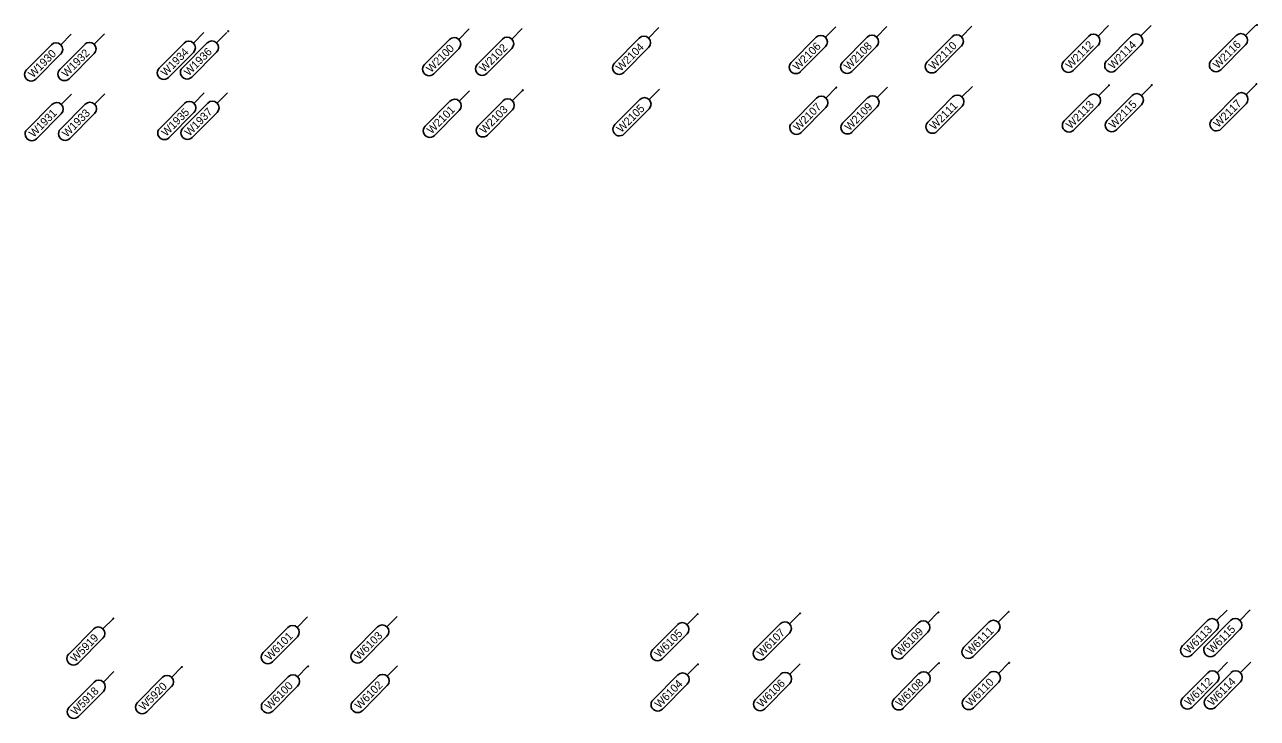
# Model space of a CAD drawing. Extents: x 12479652 to 12487250, y 9842710 to 9846560.
# Drawn here: x 12483450.8 to 12483643.4, y 9842744 to 9842852.3 of the extents above; entities that cross this region are included whole.
import ezdxf

# ---------------------------------------------------------------- set-up
doc = ezdxf.new("R2010")
doc.units = 0
doc.layers.add('_CIVIL_CONSTRUCTION', color=7, linetype='Continuous')
doc.layers.add('TextAlignmentLrg', color=7, linetype='Continuous')

msp = doc.modelspace()

# ---------------------------------------------------------------- linework, layer by layer
at = {"layer": '_CIVIL_CONSTRUCTION'}
for p, q in [((12483478.81, 9842851.1), (12483477.19, 9842849.47)), ((12483482.43, 9842851.14), (12483480.81, 9842849.51)), ((12483520.26, 9842851.67), (12483518.64, 9842850.04)), ((12483528.55, 9842851.73), (12483526.93, 9842850.1)), ((12483549.91, 9842851.88), (12483548.29, 9842850.25)), ((12483577.52, 9842852.01), (12483575.9, 9842850.37)), ((12483585.52, 9842852.04), (12483583.9, 9842850.41)), ((12483598.78, 9842852.1), (12483597.16, 9842850.47)), ((12483620.1, 9842852.2), (12483618.48, 9842850.57)), ((12483626.8, 9842852.23), (12483625.18, 9842850.6)), ((12483643.14, 9842852.28), (12483641.52, 9842850.65)), ((12483451.14, 9842845.3), (12483455.03, 9842849.21)), ((12483456.34, 9842845.36), (12483460.23, 9842849.27)), ((12483458.1, 9842850.85), (12483456.48, 9842849.22)), ((12483463.3, 9842850.91), (12483461.68, 9842849.28)), ((12483471.85, 9842845.55), (12483475.74, 9842849.46)), ((12483475.47, 9842845.59), (12483479.36, 9842849.51)), ((12483513.3, 9842846.12), (12483517.19, 9842850.04)), ((12483521.59, 9842846.18), (12483525.48, 9842850.09)), ((12483542.95, 9842846.33), (12483546.84, 9842850.24)), ((12483570.56, 9842846.46), (12483574.45, 9842850.37)), ((12483578.56, 9842846.49), (12483582.45, 9842850.41)), ((12483591.82, 9842846.55), (12483595.7, 9842850.47)), ((12483613.14, 9842846.65), (12483617.03, 9842850.56)), ((12483619.84, 9842846.68), (12483623.73, 9842850.59)), ((12483625.18, 9842849.15), (12483621.29, 9842845.23)), ((12483636.18, 9842846.73), (12483640.07, 9842850.64)), ((12483641.52, 9842849.2), (12483637.64, 9842845.28)), ((12483456.48, 9842847.77), (12483452.59, 9842843.85)), ((12483461.69, 9842847.83), (12483457.8, 9842843.91)), ((12483477.2, 9842848.01), (12483473.31, 9842844.1)), ((12483480.82, 9842848.06), (12483476.93, 9842844.15)), ((12483518.64, 9842848.59), (12483514.75, 9842844.68)), ((12483526.93, 9842848.65), (12483523.04, 9842844.73)), ((12483548.29, 9842848.8), (12483544.4, 9842844.88)), ((12483575.91, 9842848.92), (12483572.02, 9842845.01)), ((12483583.9, 9842848.96), (12483580.01, 9842845.05)), ((12483597.16, 9842849.02), (12483593.27, 9842845.11)), ((12483618.49, 9842849.12), (12483614.6, 9842845.2)), ((12483458.18, 9842841.52), (12483456.56, 9842839.89)), ((12483463.38, 9842841.57), (12483461.76, 9842839.93)), ((12483478.89, 9842841.69), (12483477.27, 9842840.06)), ((12483482.51, 9842841.72), (12483480.89, 9842840.09)), ((12483520.34, 9842842.04), (12483518.72, 9842840.41)), ((12483528.63, 9842842.11), (12483527.01, 9842840.48)), ((12483549.99, 9842842.29), (12483548.37, 9842840.65)), ((12483577.6, 9842842.51), (12483575.98, 9842840.88)), ((12483585.6, 9842842.58), (12483583.98, 9842840.95)), ((12483598.86, 9842842.69), (12483597.23, 9842841.06)), ((12483620.18, 9842842.87), (12483618.56, 9842841.24)), ((12483626.88, 9842842.92), (12483625.25, 9842841.29)), ((12483636.26, 9842837.51), (12483640.15, 9842841.42)), ((12483643.22, 9842843.06), (12483641.6, 9842841.43)), ((12483451.22, 9842835.97), (12483455.1, 9842839.89)), ((12483456.42, 9842836.02), (12483460.31, 9842839.93)), ((12483471.93, 9842836.15), (12483475.82, 9842840.06)), ((12483475.55, 9842836.18), (12483479.44, 9842840.09)), ((12483513.38, 9842836.49), (12483517.27, 9842840.4)), ((12483521.67, 9842836.56), (12483525.56, 9842840.47)), ((12483543.03, 9842836.74), (12483546.92, 9842840.65)), ((12483570.64, 9842836.97), (12483574.53, 9842840.88)), ((12483578.64, 9842837.03), (12483582.53, 9842840.95)), ((12483583.98, 9842839.5), (12483580.09, 9842835.59)), ((12483591.89, 9842837.14), (12483595.78, 9842841.06)), ((12483597.24, 9842839.61), (12483593.35, 9842835.7)), ((12483613.22, 9842837.32), (12483617.11, 9842841.23)), ((12483618.56, 9842839.79), (12483614.67, 9842835.87)), ((12483619.91, 9842837.38), (12483623.8, 9842841.29)), ((12483625.26, 9842839.84), (12483621.37, 9842835.93)), ((12483641.6, 9842839.98), (12483637.71, 9842836.06)), ((12483456.56, 9842838.44), (12483452.67, 9842834.53)), ((12483461.76, 9842838.48), (12483457.87, 9842834.57)), ((12483477.27, 9842838.61), (12483473.38, 9842834.7)), ((12483480.89, 9842838.64), (12483477, 9842834.73)), ((12483518.72, 9842838.96), (12483514.83, 9842835.04)), ((12483527.01, 9842839.03), (12483523.12, 9842835.11)), ((12483548.37, 9842839.2), (12483544.48, 9842835.29)), ((12483575.99, 9842839.43), (12483572.1, 9842835.52)), ((12483593.53, 9842760.59), (12483591.91, 9842758.96)), ((12483604.49, 9842760.68), (12483602.87, 9842759.04)), ((12483638.64, 9842760.93), (12483637.01, 9842759.3)), ((12483642.27, 9842760.96), (12483640.65, 9842759.33)), ((12483464.69, 9842759.63), (12483463.07, 9842758)), ((12483495.04, 9842759.86), (12483493.42, 9842758.23)), ((12483509.04, 9842759.96), (12483507.42, 9842758.33)), ((12483548.95, 9842754.76), (12483552.84, 9842758.68)), ((12483555.91, 9842760.31), (12483554.29, 9842758.68)), ((12483564.95, 9842754.88), (12483568.84, 9842758.8)), ((12483571.91, 9842760.43), (12483570.29, 9842758.8)), ((12483586.57, 9842755.04), (12483590.46, 9842758.96)), ((12483597.53, 9842755.13), (12483601.42, 9842759.04)), ((12483631.67, 9842755.38), (12483635.56, 9842759.29)), ((12483635.31, 9842755.41), (12483639.2, 9842759.32)), ((12483457.73, 9842754.08), (12483461.62, 9842758)), ((12483488.08, 9842754.31), (12483491.97, 9842758.22)), ((12483493.43, 9842756.78), (12483489.54, 9842752.86)), ((12483502.08, 9842754.41), (12483505.97, 9842758.33)), ((12483507.43, 9842756.88), (12483503.54, 9842752.97)), ((12483554.29, 9842757.23), (12483550.4, 9842753.32)), ((12483570.29, 9842757.35), (12483566.4, 9842753.44)), ((12483591.91, 9842757.51), (12483588.02, 9842753.6)), ((12483602.87, 9842757.59), (12483598.99, 9842753.68)), ((12483637.02, 9842757.85), (12483633.13, 9842753.94)), ((12483640.65, 9842757.88), (12483636.76, 9842753.96)), ((12483463.07, 9842756.55), (12483459.18, 9842752.64)), ((12483464.75, 9842751.33), (12483463.13, 9842749.7)), ((12483475.41, 9842752.06), (12483473.79, 9842750.43)), ((12483495.08, 9842752.16), (12483493.46, 9842750.53)), ((12483509.08, 9842752.23), (12483507.46, 9842750.6)), ((12483555.95, 9842752.46), (12483554.32, 9842750.83)), ((12483571.95, 9842752.54), (12483570.32, 9842750.9)), ((12483586.63, 9842747.09), (12483590.52, 9842751.01)), ((12483593.59, 9842752.64), (12483591.97, 9842751.01)), ((12483597.59, 9842747.15), (12483601.48, 9842751.06)), ((12483604.55, 9842752.7), (12483602.93, 9842751.06)), ((12483631.73, 9842747.24), (12483635.62, 9842751.15)), ((12483635.37, 9842747.25), (12483639.26, 9842751.16)), ((12483638.7, 9842752.79), (12483637.07, 9842751.16)), ((12483642.33, 9842752.8), (12483640.71, 9842751.17)), ((12483457.79, 9842745.78), (12483461.68, 9842749.7)), ((12483468.45, 9842746.52), (12483472.34, 9842750.43)), ((12483488.12, 9842746.61), (12483492.01, 9842750.52)), ((12483493.46, 9842749.08), (12483489.58, 9842745.17)), ((12483502.12, 9842746.68), (12483506.01, 9842750.59)), ((12483507.47, 9842749.15), (12483503.58, 9842745.23)), ((12483548.98, 9842746.91), (12483552.87, 9842750.82)), ((12483554.33, 9842749.38), (12483550.44, 9842745.46)), ((12483564.98, 9842746.99), (12483568.87, 9842750.9)), ((12483570.33, 9842749.45), (12483566.44, 9842745.54)), ((12483591.97, 9842749.56), (12483588.08, 9842745.65)), ((12483602.93, 9842749.61), (12483599.04, 9842745.7)), ((12483637.08, 9842749.71), (12483633.19, 9842745.79)), ((12483640.71, 9842749.71), (12483636.82, 9842745.8)), ((12483463.13, 9842748.25), (12483459.24, 9842744.34)), ((12483473.8, 9842748.98), (12483469.91, 9842745.07))]:
    msp.add_line(p, q, dxfattribs=at)
for centre, start, end in [((12483455.76, 9842848.49), 315.1702, 135.1702), ((12483460.96, 9842848.55), 315.1702, 135.1702), ((12483476.47, 9842848.74), 315.1702, 135.1702), ((12483480.09, 9842848.78), 315.1702, 135.1702), ((12483517.91, 9842849.31), 315.1702, 135.1702), ((12483526.2, 9842849.37), 315.1702, 135.1702), ((12483547.57, 9842849.52), 315.1702, 135.1702), ((12483575.18, 9842849.65), 315.1702, 135.1702), ((12483583.18, 9842849.68), 315.1702, 135.1702), ((12483596.43, 9842849.74), 315.1702, 135.1702), ((12483617.76, 9842849.84), 315.1702, 135.1702), ((12483624.45, 9842849.87), 315.1702, 135.1702), ((12483640.8, 9842849.92), 315.1702, 135.1702), ((12483451.87, 9842844.58), 135.1702, 315.1702), ((12483457.07, 9842844.64), 135.1702, 315.1702), ((12483472.58, 9842844.83), 135.1702, 315.1702), ((12483476.2, 9842844.87), 135.1702, 315.1702), ((12483514.03, 9842845.4), 135.1702, 315.1702), ((12483522.31, 9842845.46), 135.1702, 315.1702), ((12483543.68, 9842845.61), 135.1702, 315.1702), ((12483571.29, 9842845.73), 135.1702, 315.1702), ((12483579.29, 9842845.77), 135.1702, 315.1702), ((12483592.54, 9842845.83), 135.1702, 315.1702), ((12483613.87, 9842845.93), 135.1702, 315.1702), ((12483620.56, 9842845.96), 135.1702, 315.1702), ((12483636.91, 9842846.01), 135.1702, 315.1702), ((12483617.84, 9842840.51), 315.1702, 135.1702), ((12483624.53, 9842840.56), 315.1702, 135.1702), ((12483640.87, 9842840.7), 315.1702, 135.1702), ((12483455.83, 9842839.16), 315.1702, 135.1702), ((12483461.04, 9842839.21), 315.1702, 135.1702), ((12483476.55, 9842839.34), 315.1702, 135.1702), ((12483480.17, 9842839.37), 315.1702, 135.1702), ((12483517.99, 9842839.68), 315.1702, 135.1702), ((12483526.28, 9842839.75), 315.1702, 135.1702), ((12483547.65, 9842839.93), 315.1702, 135.1702), ((12483575.26, 9842840.16), 315.1702, 135.1702), ((12483583.26, 9842840.22), 315.1702, 135.1702), ((12483596.51, 9842840.33), 315.1702, 135.1702), ((12483451.94, 9842835.25), 135.1702, 315.1702), ((12483457.15, 9842835.29), 135.1702, 315.1702), ((12483472.66, 9842835.42), 135.1702, 315.1702), ((12483476.28, 9842835.45), 135.1702, 315.1702), ((12483514.11, 9842835.77), 135.1702, 315.1702), ((12483522.39, 9842835.84), 135.1702, 315.1702), ((12483543.76, 9842836.01), 135.1702, 315.1702), ((12483571.37, 9842836.24), 135.1702, 315.1702), ((12483579.37, 9842836.31), 135.1702, 315.1702), ((12483592.62, 9842836.42), 135.1702, 315.1702), ((12483613.95, 9842836.6), 135.1702, 315.1702), ((12483620.64, 9842836.65), 135.1702, 315.1702), ((12483636.98, 9842836.79), 135.1702, 315.1702), ((12483553.56, 9842757.95), 315.1702, 135.1702), ((12483569.56, 9842758.07), 315.1702, 135.1702), ((12483591.19, 9842758.23), 315.1702, 135.1702), ((12483602.15, 9842758.32), 315.1702, 135.1702), ((12483636.29, 9842758.57), 315.1702, 135.1702), ((12483639.92, 9842758.6), 315.1702, 135.1702), ((12483462.34, 9842757.27), 315.1702, 135.1702), ((12483492.7, 9842757.5), 315.1702, 135.1702), ((12483506.7, 9842757.6), 315.1702, 135.1702), ((12483565.67, 9842754.16), 135.1702, 315.1702), ((12483587.3, 9842754.32), 135.1702, 315.1702), ((12483598.26, 9842754.4), 135.1702, 315.1702), ((12483632.4, 9842754.66), 135.1702, 315.1702), ((12483636.03, 9842754.69), 135.1702, 315.1702), ((12483458.45, 9842753.36), 135.1702, 315.1702), ((12483488.81, 9842753.59), 135.1702, 315.1702), ((12483502.81, 9842753.69), 135.1702, 315.1702), ((12483549.67, 9842754.04), 135.1702, 315.1702), ((12483553.6, 9842750.1), 315.1702, 135.1702), ((12483569.6, 9842750.18), 315.1702, 135.1702), ((12483591.25, 9842750.28), 315.1702, 135.1702), ((12483602.21, 9842750.34), 315.1702, 135.1702), ((12483636.35, 9842750.43), 315.1702, 135.1702), ((12483639.98, 9842750.44), 315.1702, 135.1702), ((12483462.41, 9842748.97), 315.1702, 135.1702), ((12483473.07, 9842749.71), 315.1702, 135.1702), ((12483492.74, 9842749.8), 315.1702, 135.1702), ((12483506.74, 9842749.87), 315.1702, 135.1702), ((12483587.36, 9842746.37), 135.1702, 315.1702), ((12483598.32, 9842746.42), 135.1702, 315.1702), ((12483632.46, 9842746.52), 135.1702, 315.1702), ((12483636.09, 9842746.53), 135.1702, 315.1702), ((12483458.52, 9842745.06), 135.1702, 315.1702), ((12483469.18, 9842745.79), 135.1702, 315.1702), ((12483488.85, 9842745.89), 135.1702, 315.1702), ((12483502.85, 9842745.96), 135.1702, 315.1702), ((12483549.71, 9842746.19), 135.1702, 315.1702), ((12483565.71, 9842746.26), 135.1702, 315.1702)]:
    msp.add_arc(centre, 1.03, start, end, dxfattribs=at)
at = {"layer": 'TextAlignmentLrg'}
for centre in [(12483482.62, 9842851.33), (12483643.32, 9842852.3), (12483528.65, 9842842.12), (12483577.62, 9842842.53), (12483620.2, 9842842.89), (12483626.89, 9842842.94), (12483643.24, 9842843.08), (12483593.58, 9842760.59), (12483604.54, 9842760.68), (12483464.69, 9842759.63), (12483555.96, 9842760.31), (12483571.96, 9842760.43), (12483475.41, 9842752.06), (12483495.13, 9842752.16), (12483556, 9842752.46), (12483593.64, 9842752.64), (12483604.6, 9842752.7)]:
    msp.add_circle(centre, 0.05, dxfattribs=at)

# ---------------------------------------------------------------- texts
at = {"layer": '_CIVIL_CONSTRUCTION'}
for s, p in [('W2100', (12483514.3, 9842844.77)), ('W2102', (12483522.61, 9842844.85)), ('W2104', (12483543.94, 9842844.97)), ('W2106', (12483571.56, 9842845.1)), ('W2108', (12483579.56, 9842845.14)), ('W2110', (12483592.81, 9842845.2)), ('W2112', (12483614.16, 9842845.32)), ('W2114', (12483620.83, 9842845.32)), ('W2116', (12483637.18, 9842845.38)), ('W1930', (12483452.14, 9842843.95)), ('W1932', (12483457.36, 9842844.03)), ('W1934', (12483472.84, 9842844.19)), ('W1936', (12483476.47, 9842844.24)), ('W2101', (12483514.41, 9842835.18)), ('W2103', (12483522.67, 9842835.22)), ('W2105', (12483544.04, 9842835.4)), ('W2107', (12483571.65, 9842835.63)), ('W2109', (12483579.64, 9842835.68)), ('W2111', (12483592.93, 9842835.83)), ('W2113', (12483614.23, 9842835.98)), ('W2115', (12483620.92, 9842836.04)), ('W2117', (12483637.27, 9842836.17)), ('W1931', (12483452.25, 9842834.66)), ('W1933', (12483457.43, 9842834.67)), ('W1935', (12483472.94, 9842834.81)), ('W1937', (12483476.56, 9842834.84)), ('W5919', (12483458.73, 9842752.73)), ('W6101', (12483489.12, 9842752.99)), ('W6103', (12483503.09, 9842753.07)), ('W6105', (12483549.96, 9842753.43)), ('W6107', (12483565.96, 9842753.54)), ('W6109', (12483587.57, 9842753.7)), ('W6111', (12483598.56, 9842753.81)), ('W6113', (12483632.68, 9842754.04)), ('W6115', (12483636.32, 9842754.07)), ('W5920', (12483469.45, 9842745.16)), ('W6100', (12483489.12, 9842745.26)), ('W6102', (12483503.14, 9842745.35)), ('W6104', (12483549.98, 9842745.55)), ('W6106', (12483565.98, 9842745.63)), ('W6108', (12483587.63, 9842745.74)), ('W6110', (12483598.59, 9842745.8)), ('W6112', (12483632.75, 9842745.91)), ('W6114', (12483636.36, 9842745.89)), ('W5918', (12483458.79, 9842744.43))]:
    msp.add_text(s, height=1.25, rotation=45.1702, dxfattribs=at).set_placement(p)

doc.saveas('drawing.dxf')
